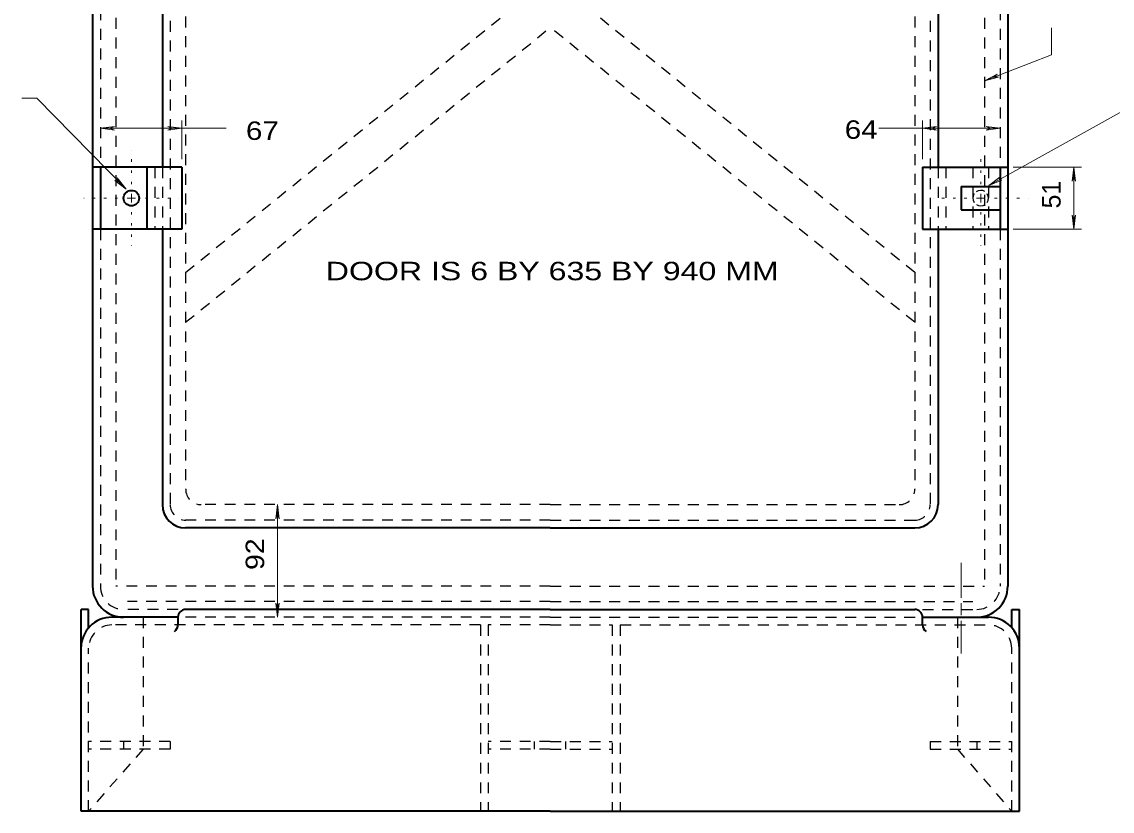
# Model space of a CAD drawing. Extents: x 312583 to 312854, y 144419 to 144597.
# Drawn here: x 312630.39 to 312675.3, y 144457.11 to 144489.6 of the extents above; entities that cross this region are included whole.
import ezdxf
from ezdxf.enums import TextEntityAlignment as Align

# ---------------------------------------------------------------- set-up
doc = ezdxf.new("R2010")
doc.units = 0
doc.header["$LTSCALE"] = 0.3
doc.linetypes.add('DOTTED', pattern=[1.5, 0.3, -1.2])
doc.linetypes.add('SHORT_DASHED', pattern=[2.7, 1.5, -1.2])
doc.layers.add('1', color=7, linetype='Continuous', lineweight=25)
doc.layers.add('2', color=7, linetype='Continuous', lineweight=13)

msp = doc.modelspace()

# ---------------------------------------------------------------- linework, layer by layer
at = {"layer": '1', "lineweight": 40}
for p, q in [((312633.3048, 144518.1223), (312633.3048, 144466.3723)), ((312671.0018, 144518.1223), (312671.0018, 144466.3723)), ((312636.1798, 144504.7057), (312636.1798, 144483.6223)), ((312668.1268, 144504.7057), (312668.1268, 144483.6223)), ((312636.9771, 144483.6223), (312633.3048, 144483.6223)), ((312633.6268, 144483.6223), (312633.6268, 144481.0693)), ((312635.5434, 144483.6223), (312635.5434, 144481.0693)), ((312636.9771, 144483.6223), (312636.9771, 144481.0693)), ((312667.4904, 144483.6223), (312671.0018, 144483.6223)), ((312667.4904, 144483.6223), (312667.4904, 144481.0693)), ((312670.6798, 144483.6223), (312670.6798, 144481.0693)), ((312669.0851, 144482.825), (312669.0851, 144481.8667)), ((312669.0851, 144482.825), (312670.6798, 144482.825)), ((312669.0851, 144481.8667), (312670.6798, 144481.8667)), ((312636.9771, 144481.0693), (312633.3048, 144481.0693)), ((312636.1798, 144481.0693), (312636.1798, 144469.7303)), ((312667.4904, 144481.0693), (312671.0018, 144481.0693)), ((312668.1268, 144481.0693), (312668.1268, 144469.7303)), ((312652.1571, 144468.772), (312637.1381, 144468.772)), ((312652.1571, 144468.772), (312667.1684, 144468.772)), ((312632.8294, 144457.111), (312632.8294, 144465.414)), ((312633.1438, 144465.414), (312632.8294, 144465.414)), ((312633.1438, 144464.6627), (312633.1438, 144465.414)), ((312652.1571, 144465.414), (312637.1381, 144465.414)), ((312652.1571, 144465.414), (312667.1684, 144465.414)), ((312671.1628, 144465.414), (312671.4771, 144465.414)), ((312671.1628, 144464.6627), (312671.1628, 144465.414)), ((312671.4771, 144457.111), (312671.4771, 144465.414)), ((312636.8238, 144465.0997), (312634.1021, 144465.0997)), ((312636.8238, 144464.7777), (312636.8238, 144465.0997)), ((312667.4904, 144465.0997), (312670.2044, 144465.0997)), ((312667.4904, 144464.7777), (312667.4904, 144465.0997)), ((312652.1571, 144457.111), (312632.8294, 144457.111)), ((312652.1571, 144457.111), (312671.4771, 144457.111))]:
    msp.add_line(p, q, dxfattribs=at)
at = {"layer": '1', "linetype": 'SHORT_DASHED'}
for p, q in [((312634.2631, 144518.1223), (312634.2631, 144466.3723)), ((312670.0434, 144518.1223), (312670.0434, 144466.3723)), ((312636.5018, 144515.5693), (312636.5018, 144469.7303)), ((312667.8048, 144515.5693), (312667.8048, 144469.7303)), ((312637.1381, 144514.933), (312637.1381, 144470.3667)), ((312667.1684, 144514.933), (312667.1684, 144470.3667)), ((312633.6268, 144504.7057), (312633.6268, 144483.6223)), ((312670.6798, 144504.7057), (312670.6798, 144483.6223)), ((312637.1381, 144479.2907), (312650.8001, 144490.3307)), ((312667.1684, 144479.2907), (312653.5064, 144490.3307)), ((312637.1381, 144477.236), (312652.1571, 144489.3723)), ((312667.1684, 144477.236), (312652.1571, 144489.3723)), ((312635.8654, 144483.6223), (312635.8654, 144481.0693)), ((312636.1798, 144483.6223), (312636.1798, 144481.0693)), ((312668.1268, 144483.6223), (312668.1268, 144481.0693)), ((312668.4488, 144483.6223), (312668.4488, 144481.0693)), ((312669.5604, 144483.6223), (312669.5604, 144481.0693)), ((312670.2044, 144483.6223), (312670.2044, 144481.0693)), ((312633.6268, 144481.0693), (312633.6268, 144466.3723)), ((312670.6798, 144481.0693), (312670.6798, 144466.3723)), ((312652.1571, 144469.7303), (312637.7821, 144469.7303)), ((312652.1571, 144469.7303), (312666.5321, 144469.7303)), ((312652.1571, 144469.0863), (312637.1381, 144469.0863)), ((312652.1571, 144469.0863), (312667.1684, 144469.0863)), ((312652.1571, 144466.3723), (312634.2631, 144466.3723)), ((312652.1571, 144466.3723), (312670.0434, 144466.3723)), ((312636.8238, 144465.414), (312634.5851, 144465.414)), ((312652.1571, 144465.736), (312634.7461, 144465.736)), ((312652.1571, 144465.736), (312669.5604, 144465.736)), ((312667.4904, 144465.414), (312669.7214, 144465.414)), ((312652.1571, 144465.0997), (312636.8238, 144465.0997)), ((312652.1571, 144465.0997), (312667.4904, 144465.0997)), ((312649.2821, 144464.7777), (312634.1021, 144464.7777)), ((312649.2821, 144464.7777), (312649.2821, 144457.111)), ((312649.5964, 144464.7777), (312649.5964, 144457.111)), ((312652.1571, 144464.7777), (312649.5964, 144464.7777)), ((312652.1571, 144464.7777), (312654.7101, 144464.7777)), ((312654.7101, 144464.7777), (312654.7101, 144457.111)), ((312655.0321, 144464.7777), (312655.0321, 144457.111)), ((312655.0321, 144464.7777), (312670.2044, 144464.7777)), ((312633.1438, 144457.111), (312633.1438, 144463.8193)), ((312671.1628, 144457.111), (312671.1628, 144463.8193)), ((312636.5018, 144459.986), (312633.1438, 144459.986)), ((312634.5851, 144459.986), (312634.5851, 144459.664)), ((312636.5018, 144459.986), (312636.5018, 144459.664)), ((312652.1571, 144459.986), (312649.5964, 144459.986)), ((312651.5131, 144459.664), (312651.5131, 144459.986)), ((312652.1571, 144459.986), (312654.7101, 144459.986)), ((312652.7934, 144459.664), (312652.7934, 144459.986)), ((312667.8048, 144459.986), (312671.1628, 144459.986)), ((312667.8048, 144459.986), (312667.8048, 144459.664)), ((312669.7214, 144459.986), (312669.7214, 144459.664)), ((312636.5018, 144459.664), (312633.1438, 144459.664)), ((312652.1571, 144459.664), (312649.5964, 144459.664)), ((312652.1571, 144459.664), (312654.7101, 144459.664)), ((312667.8048, 144459.664), (312671.1628, 144459.664))]:
    msp.add_line(p, q, dxfattribs=at)
at = {"layer": '1', "linetype": 'DOTTED', "lineweight": 13}
for p, q in [((312634.9071, 144482.9247), (312634.9071, 144484.3047)), ((312669.8824, 144482.9247), (312669.8824, 144484.3047)), ((312634.3321, 144482.3497), (312632.9444, 144482.3497)), ((312635.4821, 144482.3497), (312636.8621, 144482.3497)), ((312669.3074, 144482.3497), (312667.9274, 144482.3497)), ((312670.4574, 144482.3497), (312671.8451, 144482.3497)), ((312634.9071, 144481.7747), (312634.9071, 144480.387)), ((312669.8824, 144481.7747), (312669.8824, 144480.387))]:
    msp.add_line(p, q, dxfattribs=at)
at = {"layer": '1', "lineweight": 13}
for p, q in [((312634.9071, 144482.3497), (312634.9071, 144482.5183)), ((312669.8824, 144482.3497), (312669.8824, 144482.5183)), ((312634.9071, 144482.3497), (312634.7308, 144482.3497)), ((312634.9071, 144482.3497), (312635.0758, 144482.3497)), ((312634.9071, 144482.3497), (312634.9071, 144482.1733)), ((312669.8824, 144482.3497), (312669.7138, 144482.3497)), ((312669.8824, 144482.3497), (312670.0511, 144482.3497)), ((312669.8824, 144482.3497), (312669.8824, 144482.1733))]:
    msp.add_line(p, q, dxfattribs=at)
at = {"layer": '1', "linetype": 'SHORT_DASHED'}
for points in [[(312635.3824, 144465.0997), (312635.3824, 144459.664), (312633.1438, 144457.111)], [(312668.9241, 144465.0997), (312668.9241, 144459.664), (312671.1628, 144457.111)]]:
    msp.add_lwpolyline(points, dxfattribs=at)
at = {"layer": '1', "lineweight": 40}
msp.add_circle((312634.9033, 144482.3471), 0.3194, dxfattribs=at)
at = {"layer": '1'}
for start, end in [(145.14079, 213.35403), (56.61149, 126.70759), (326.83677, 32.29727), (236.53462, 306.15074)]:
    msp.add_arc((312669.8824, 144482.3471), 0.3194, start, end, dxfattribs=at)
at = {"layer": '1', "linetype": 'SHORT_DASHED'}
for centre, radius, start, end in [((312637.7783, 144470.3679), 0.6389, 180, 270), ((312666.5283, 144470.3679), 0.6389, 270, 0), ((312637.1394, 144469.7291), 0.6389, 180, 270), ((312667.1672, 144469.7291), 0.6389, 270, 0), ((312634.5838, 144466.3749), 0.9583, 180, 270), ((312669.7227, 144466.3749), 0.9583, 270, 0), ((312634.1047, 144463.8193), 0.9583, 90, 180), ((312670.2019, 144463.8193), 0.9583, 0, 90)]:
    msp.add_arc(centre, radius, start, end, dxfattribs=at)
at = {"layer": '1', "lineweight": 40}
for centre, radius, start, end in [((312637.1394, 144469.7291), 0.9583, 180, 270), ((312667.1672, 144469.7291), 0.9583, 270, 0), ((312634.5838, 144466.3749), 1.2778, 180, 270), ((312669.7227, 144466.3749), 1.2778, 270, 0), ((312637.1394, 144465.0971), 0.3194, 90, 180), ((312667.1672, 144465.0971), 0.3194, 0, 90), ((312634.1047, 144463.8193), 1.2778, 90, 180), ((312670.2019, 144463.8193), 1.2778, 0, 90), ((312636.5005, 144464.7777), 0.3194, 302.70422, 0), ((312667.806, 144464.7777), 0.3194, 180, 237.29578)]:
    msp.add_arc(centre, radius, start, end, dxfattribs=at)
at = {"layer": '2'}
for p, q in [((312672.8034, 144489.357), (312672.8034, 144488.2453)), ((312672.8034, 144488.2453), (312670.0434, 144487.1797)), ((312670.0434, 144487.1797), (312670.5571, 144487.4557)), ((312670.0434, 144487.1797), (312670.6108, 144487.3253)), ((312670.5571, 144487.4557), (312670.4114, 144487.3253)), ((312670.6108, 144487.3253), (312670.4114, 144487.3253)), ((312630.3906, 144486.459), (312631.0048, 144486.459)), ((312631.0048, 144486.459), (312634.6848, 144482.71)), ((312636.9771, 144483.9443), (312636.9771, 144485.539)), ((312667.4904, 144483.9443), (312667.4904, 144485.539)), ((312633.6268, 144485.2247), (312634.2018, 144485.2937)), ((312638.8018, 144485.2247), (312633.6268, 144485.2247)), ((312633.6268, 144485.2247), (312634.2018, 144485.148)), ((312634.2018, 144485.2937), (312634.0178, 144485.2247)), ((312634.2018, 144485.148), (312634.0178, 144485.2247)), ((312636.4021, 144485.2937), (312636.5861, 144485.2247)), ((312636.9771, 144485.2247), (312636.4021, 144485.2937)), ((312636.4021, 144485.148), (312636.5861, 144485.2247)), ((312636.9771, 144485.2247), (312636.4021, 144485.148)), ((312665.6888, 144485.2247), (312670.6798, 144485.2247)), ((312667.4904, 144485.2247), (312668.0654, 144485.2937)), ((312667.4904, 144485.2247), (312668.0654, 144485.148)), ((312668.0654, 144485.2937), (312667.8814, 144485.2247)), ((312668.0654, 144485.148), (312667.8814, 144485.2247)), ((312670.1048, 144485.2937), (312670.2888, 144485.2247)), ((312670.6798, 144485.2247), (312670.1048, 144485.2937)), ((312670.1048, 144485.148), (312670.2888, 144485.2247)), ((312670.6798, 144485.2247), (312670.1048, 144485.148)), ((312671.2241, 144483.6223), (312674.0378, 144483.6223)), ((312673.7158, 144483.6223), (312673.6468, 144483.0473)), ((312673.7158, 144481.0693), (312673.7158, 144483.6223)), ((312673.7158, 144483.6223), (312673.7848, 144483.0473)), ((312634.2248, 144483.078), (312634.4088, 144482.9937)), ((312634.6848, 144482.71), (312634.2248, 144483.078)), ((312634.3244, 144483.1777), (312634.4088, 144482.9937)), ((312634.6848, 144482.71), (312634.3244, 144483.1777)), ((312673.6468, 144483.0473), (312673.7158, 144483.2313)), ((312673.7848, 144483.0473), (312673.7158, 144483.2313)), ((312673.6468, 144481.6443), (312673.7158, 144481.4603)), ((312673.7158, 144481.0693), (312673.6468, 144481.6443)), ((312673.7848, 144481.6443), (312673.7158, 144481.4603)), ((312673.7158, 144481.0693), (312673.7848, 144481.6443)), ((312671.2241, 144481.0693), (312674.0378, 144481.0693)), ((312640.9178, 144469.7303), (312640.8488, 144469.1477)), ((312640.9178, 144465.0997), (312640.9178, 144469.7303)), ((312640.9178, 144469.7303), (312640.9944, 144469.1477)), ((312640.8488, 144469.1477), (312640.9178, 144469.3317)), ((312640.9944, 144469.1477), (312640.9178, 144469.3317)), ((312669.0851, 144465.897), (312669.0851, 144467.3307)), ((312640.8488, 144465.6747), (312640.9178, 144465.4907)), ((312640.9178, 144465.0997), (312640.8488, 144465.6747)), ((312640.9944, 144465.6747), (312640.9178, 144465.4907)), ((312640.9178, 144465.0997), (312640.9944, 144465.6747)), ((312669.0851, 144465.1763), (312669.0851, 144465.6747)), ((312669.0851, 144463.6047), (312669.0851, 144464.9463))]:
    msp.add_line(p, q, dxfattribs=at)
msp.add_lwpolyline([(312670.2121, 144482.8633), (312676.5908, 144486.413), (312683.0538, 144482.9247)], dxfattribs=at)
msp.add_lwpolyline([(312670.7488, 144483.0857), (312670.2121, 144482.8633), (312670.6721, 144483.216), (312670.6644, 144483.1163)], close=True, dxfattribs=at)

# ---------------------------------------------------------------- texts
for s, width, p in [('64 ', 1.2, (312665.1303, 144484.7885)), ('67 ', 1.2, (312640.4688, 144484.7435)), ('DOOR IS 6 BY 635 BY 940 MM', 1.3, (312652.2362, 144478.9663))]:
    msp.add_text(s, height=0.76, dxfattribs=dict(at, width=width)).set_placement(p, align=Align.CENTER)
msp.add_text('51 ', height=0.76, rotation=90, dxfattribs=at).set_placement((312673.1747, 144482.6309), align=Align.CENTER)
at = {"layer": '2', "width": 1.15}
msp.add_text('92 ', height=0.76, rotation=90, dxfattribs=at).set_placement((312640.3711, 144467.8525), align=Align.CENTER)

doc.saveas('drawing.dxf')
